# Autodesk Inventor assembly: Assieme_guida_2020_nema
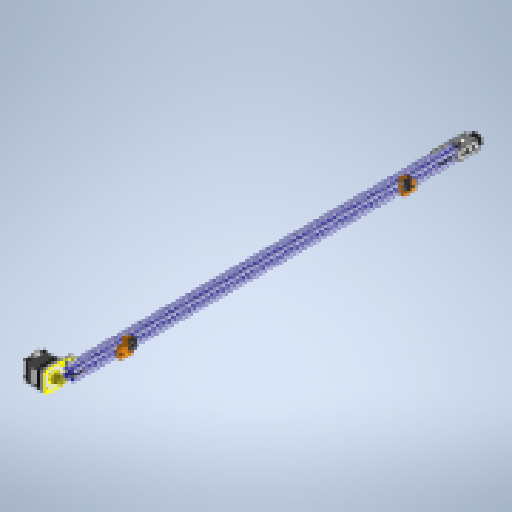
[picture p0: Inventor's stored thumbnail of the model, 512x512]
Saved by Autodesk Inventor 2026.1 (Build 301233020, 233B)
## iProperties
Created: 2026-01
Part Number: Assieme_guida_2020_nema
Document SubType Name: Assembly
Designer: hp
Sending System: Autodesk Inventor 2025
Preprocessor: ST-DEVELOPER v20
Title: Assieme_guida_2020_nema.stp
Author: R5800u
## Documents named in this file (18)
- C:\Users\hp\Documents\Inventor\DOM1_CartesianRobot\Assieme_guida_2020_nema.iam
- C:\Users\hp\Documents\Inventor\DOM1_CartesianRobot\2020.ipt
- C:\Users\hp\Documents\Inventor\DOM1_CartesianRobot\2020 Belt Tensioner G_K.iam
- C:\Users\hp\Documents\Inventor\DOM1_CartesianRobot\GT2_20T.ipt
- C:\Users\hp\Documents\Inventor\DOM1_CartesianRobot\NO-NC Limit Switch.ipt
- C:\Users\hp\Documents\Inventor\DOM1_CartesianRobot\blocco_sensore.ipt
- C:\Users\hp\Documents\Inventor\DOM1_CartesianRobot\blocco_sensore_MIR.ipt
- C:\Users\hp\Documents\Inventor\DOM1_CartesianRobot\NEMA 42SHDC3030Z.ipt
- C:\Users\hp\Documents\Inventor\DOM1_CartesianRobot\blocco_nema.ipt
- C:\Users\hp\Documents\Inventor\Content Center Files\R2026\en-US\ISO 4032(2)\ISO 4032 - M3 - ISO.ipt
- C:\Users\hp\Documents\Inventor\DOM1_CartesianRobot\2020 M3.ipt
- C:\Users\hp\Documents\Inventor\DOM1_CartesianRobot\2020 M4 (1).ipt
- C:\Users\hp\Documents\Inventor\Content Center Files\R2026\en-US\ISO 4017(1)\ISO 4017 - M2 x 16 - ISO.ipt
- C:\Users\hp\Documents\Inventor\Content Center Files\R2026\en-US\ISO 4035(2)\ISO 4035 - M2 - ISO.ipt
- C:\Users\hp\Documents\Inventor\Content Center Files\R2026\en-US\ISO 4017(1)\ISO 4017 - M4 x 25 - ISO.ipt
- C:\Users\hp\Documents\Inventor\Content Center Files\R2026\en-US\ISO 4762(2)\ISO 4762 - M4 x 25ISO.ipt
- C:\Users\hp\Documents\Inventor\Content Center Files\R2026\en-US\ISO 4762(2)\ISO 4762 - M3 x 25ISO.ipt
- C:\Users\hp\Documents\Inventor\Content Center Files\R2026\en-US\ANSI B18.3.1M(2)\ANSI B18.3.1M - M3x0.5 x 45(6).ipt
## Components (41 placed, 17 different names)
1. 2020:1
2. 2020 Belt Tensioner G_K:1 [sub-assembly]
3. GT2_20T:1 — Rigid:1
4. NO-NC Limit Switch:1
5. NO-NC Limit Switch:2
6. blocco_sensore:1
7. blocco_sensore_MIR:1
8. NEMA 42SHDC3030Z:1 — Mate:1, Mate:2, Mate:3, Rigid:1, Mate:134, Mate:136, Mate:138, Mate:140
9. blocco_nema:1
10. 2020 M3:1 — Mate:63, Angle:3, Mate:118
11. 2020 M4 (1):1 — Mate:36, Angle:2, Mate:45, Mate:112
12. 2020 M3:2 — Mate:62, Angle:4, Mate:117
13. 2020 M4 (1):2 — Mate:44, Angle:1, Mate:111
14. ISO 4017 M2 x 16:1 — Mate:52, Mate:53
15. ISO 4035 M2:1 — Mate:56, Mate:57
16. ISO 4017 M2 x 16:2 — Mate:54, Mate:55
17. ISO 4035 M2:2 — Mate:58, Mate:59
18. ISO 4017 M4 x 25:1 — Mate:65, Mate:66, Mate:82
19. ISO 4017 M4 x 25:2 — Mate:67, Mate:68, Mate:81
20. ISO 4017 M2 x 16:3 — Mate:73, Mate:74
21. ISO 4035 M2:3 — Mate:77, Mate:78
22. ISO 4017 M2 x 16:4 — Mate:75, Mate:76
23. ISO 4035 M2:4 — Mate:79, Mate:80
24. 2020 M3:3 — Mate:88, Angle:9, Mate:124
25. 2020 M4 (1):3 — Mate:81, Mate:83, Angle:7
26. 2020 M4 (1):4 — Mate:82, Mate:84, Angle:6
27. 2020 M3:4 — Mate:89, Angle:8, Mate:123
28. Drilled Broached Hexagon Socket Head Cap Screw - 2 Holes - Metric M3x0.5 x 45:1 — Mate:125, Mate:126
29. ISO 4032 M3:1 — Mate:133, Mate:134
30. ISO 4762 M4 x 25:1 — Mate:107, Mate:108, Mate:112
31. ISO 4762 M4 x 25:2 — Mate:109, Mate:110, Mate:111
32. ISO 4762 M3 x 25:1 — Mate:113, Mate:114, Mate:117
33. ISO 4762 M3 x 25:2 — Mate:115, Mate:116, Mate:118
34. ISO 4762 M3 x 25:3 — Mate:119, Mate:120, Mate:124
35. ISO 4762 M3 x 25:4 — Mate:121, Mate:122, Mate:123
36. Drilled Broached Hexagon Socket Head Cap Screw - 2 Holes - Metric M3x0.5 x 45:2 — Mate:127, Mate:128
37. Drilled Broached Hexagon Socket Head Cap Screw - 2 Holes - Metric M3x0.5 x 45:3 — Mate:129, Mate:130
38. Drilled Broached Hexagon Socket Head Cap Screw - 2 Holes - Metric M3x0.5 x 45:4 — Mate:131, Mate:132
39. ISO 4032 M3:2 — Mate:135, Mate:136
40. ISO 4032 M3:3 — Mate:137, Mate:138
41. ISO 4032 M3:4 — Mate:139, Mate:140
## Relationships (77: Mate 68, Angle 8, WeldJoint 1)
- Mate:1: NEMA 42SHDC3030Z:1
- Mate:2: NEMA 42SHDC3030Z:1
- Mate:3: NEMA 42SHDC3030Z:1
- Rigid:1 [WeldJoint]: GT2_20T:1 ↔ NEMA 42SHDC3030Z:1
- Mate:36: 2020 M4 (1):1
- Mate:44: 2020 M4 (1):2
- Angle:1: 2020 M4 (1):2
- Angle:2: 2020 M4 (1):1
- Mate:45: 2020 M4 (1):1
- Mate:52: ISO 4017 M2 x 16:1
- Mate:53: ISO 4017 M2 x 16:1
- Mate:54: ISO 4017 M2 x 16:2
- Mate:55: ISO 4017 M2 x 16:2
- Mate:56: ISO 4035 M2:1
- Mate:57: ISO 4035 M2:1
- Mate:58: ISO 4035 M2:2
- Mate:59: ISO 4035 M2:2
- Mate:62: 2020 M3:2
- Mate:63: 2020 M3:1
- Angle:3: 2020 M3:1
- Angle:4: 2020 M3:2
- Mate:65: ISO 4017 M4 x 25:1
- Mate:66: ISO 4017 M4 x 25:1
- Mate:67: ISO 4017 M4 x 25:2
- Mate:68: ISO 4017 M4 x 25:2
- Mate:73: ISO 4017 M2 x 16:3
- Mate:74: ISO 4017 M2 x 16:3
- Mate:75: ISO 4017 M2 x 16:4
- Mate:76: ISO 4017 M2 x 16:4
- Mate:77: ISO 4035 M2:3
- Mate:78: ISO 4035 M2:3
- Mate:79: ISO 4035 M2:4
- Mate:80: ISO 4035 M2:4
- Mate:81: ISO 4017 M4 x 25:2 ↔ 2020 M4 (1):3
- Mate:82: ISO 4017 M4 x 25:1 ↔ 2020 M4 (1):4
- Mate:83: 2020 M4 (1):3
- Mate:84: 2020 M4 (1):4
- Angle:6: 2020 M4 (1):4
- Angle:7: 2020 M4 (1):3
- Mate:88: 2020 M3:3
- Mate:89: 2020 M3:4
- Angle:8: 2020 M3:4
- Angle:9: 2020 M3:3
- Mate:107: ISO 4762 M4 x 25:1
- Mate:108: ISO 4762 M4 x 25:1
- Mate:109: ISO 4762 M4 x 25:2
- Mate:110: ISO 4762 M4 x 25:2
- Mate:111: 2020 M4 (1):2 ↔ ISO 4762 M4 x 25:2
- Mate:112: 2020 M4 (1):1 ↔ ISO 4762 M4 x 25:1
- Mate:113: ISO 4762 M3 x 25:1
- Mate:114: ISO 4762 M3 x 25:1
- Mate:115: ISO 4762 M3 x 25:2
- Mate:116: ISO 4762 M3 x 25:2
- Mate:117: 2020 M3:2 ↔ ISO 4762 M3 x 25:1
- Mate:118: 2020 M3:1 ↔ ISO 4762 M3 x 25:2
- Mate:119: ISO 4762 M3 x 25:3
- Mate:120: ISO 4762 M3 x 25:3
- Mate:121: ISO 4762 M3 x 25:4
- Mate:122: ISO 4762 M3 x 25:4
- Mate:123: 2020 M3:4 ↔ ISO 4762 M3 x 25:4
- Mate:124: 2020 M3:3 ↔ ISO 4762 M3 x 25:3
- Mate:125: Drilled Broached Hexagon Socket Head Cap Screw - 2 Holes - Metric M3x0.5 x 45:1
- Mate:126: Drilled Broached Hexagon Socket Head Cap Screw - 2 Holes - Metric M3x0.5 x 45:1
- Mate:127: Drilled Broached Hexagon Socket Head Cap Screw - 2 Holes - Metric M3x0.5 x 45:2
- Mate:128: Drilled Broached Hexagon Socket Head Cap Screw - 2 Holes - Metric M3x0.5 x 45:2
- Mate:129: Drilled Broached Hexagon Socket Head Cap Screw - 2 Holes - Metric M3x0.5 x 45:3
- Mate:130: Drilled Broached Hexagon Socket Head Cap Screw - 2 Holes - Metric M3x0.5 x 45:3
- Mate:131: Drilled Broached Hexagon Socket Head Cap Screw - 2 Holes - Metric M3x0.5 x 45:4
- Mate:132: Drilled Broached Hexagon Socket Head Cap Screw - 2 Holes - Metric M3x0.5 x 45:4
- Mate:133: ISO 4032 M3:1
- Mate:134: NEMA 42SHDC3030Z:1 ↔ ISO 4032 M3:1
- Mate:135: ISO 4032 M3:2
- Mate:136: NEMA 42SHDC3030Z:1 ↔ ISO 4032 M3:2
- Mate:137: ISO 4032 M3:3
- Mate:138: NEMA 42SHDC3030Z:1 ↔ ISO 4032 M3:3
- Mate:139: ISO 4032 M3:4
- Mate:140: NEMA 42SHDC3030Z:1 ↔ ISO 4032 M3:4
